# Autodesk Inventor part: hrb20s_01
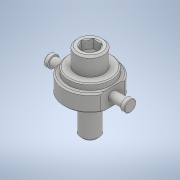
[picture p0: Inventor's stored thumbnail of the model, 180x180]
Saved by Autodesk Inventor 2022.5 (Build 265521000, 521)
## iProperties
Part Number: hrb20s_01
Material: 一般
Document SubType Name: Modeling
Designer: ImaoCorp
Density: 1 g/cm^3
Appearance: 既定
Author: ImaoCorp
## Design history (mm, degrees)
feature "hrb20s_01"
node "ソリッド1"
